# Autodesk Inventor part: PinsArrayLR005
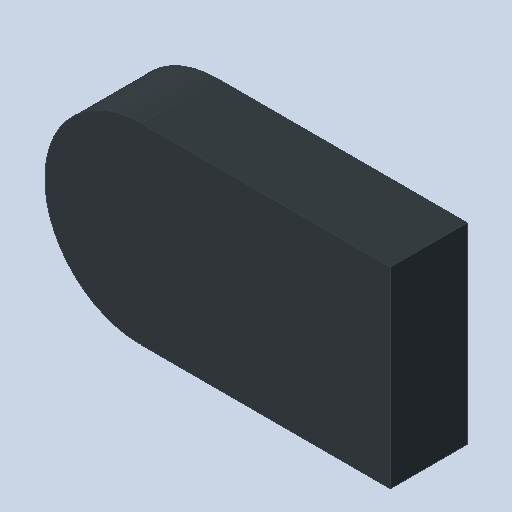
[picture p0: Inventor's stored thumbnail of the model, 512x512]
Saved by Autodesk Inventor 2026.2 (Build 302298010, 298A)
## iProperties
Created: 2026-10
Part Number: PinsArrayLR005
Material: Générique
Document SubType Name: Modeling
Designer: mel
Density: 1 g/cm^3
Appearance: Par défaut
Author: mel
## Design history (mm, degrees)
feature "Base1"
node "Solide1"
